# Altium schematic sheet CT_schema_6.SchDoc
size 287 x 160 mm
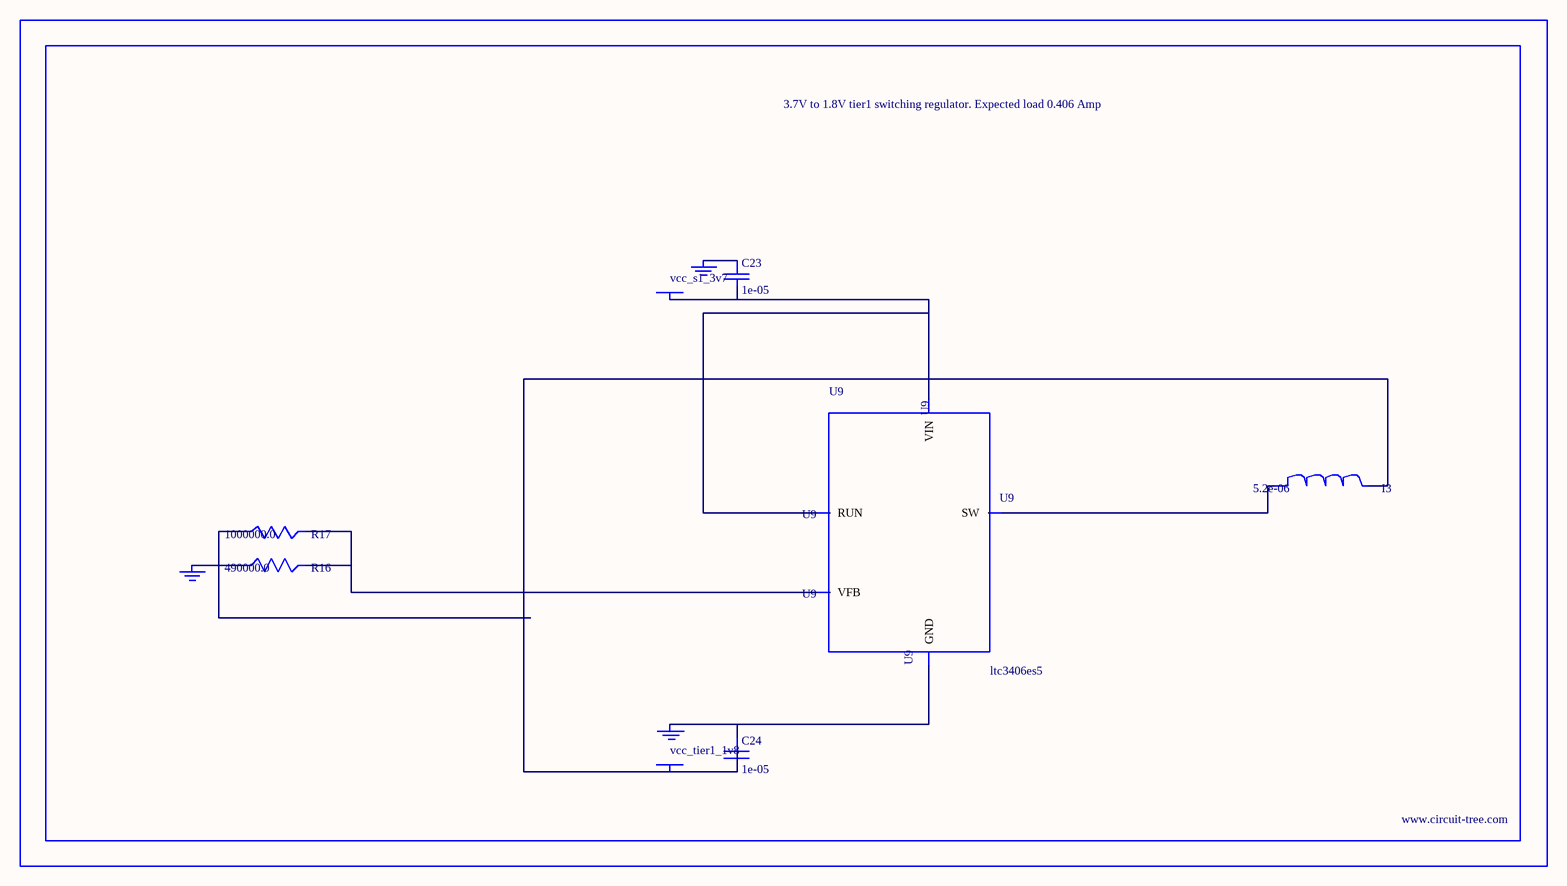
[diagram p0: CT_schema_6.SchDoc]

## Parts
BORDER5  (no value)
C23  1e-05  [C0805]
C24  1e-05  [C0805]
GND_INSTANCE_5_0  (no value)
GND_INSTANCE_5_1  (no value)
GND_INSTANCE_5_2  (no value)
I3  5.2e-06  [DR1040]
POWER_INSTANCE_5_0  vcc_tier1_1v8
POWER_INSTANCE_5_1  vcc_s1_3v7
R16  490000.0  [R0603]
R17  1000000.0  [R0603]
U9  ltc3406es5  [TSOT-23-5]

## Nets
NetC23_1: C23.1 GND_INSTANCE_5_1.0(GND)
NetC23_2: C23.2 POWER_INSTANCE_5_1.0(PWR) U9.1(RUN) U9.4(VIN)
NetC24_1: C24.1 GND_INSTANCE_5_0.0(GND) U9.2(GND)
NetC24_2: C24.2 I3.2 POWER_INSTANCE_5_0.0(PWR) R17.1
NetGND_INSTANCE_5_2_0: GND_INSTANCE_5_2.0(GND) R16.1
NetI3_1: I3.1 U9.3(SW)
NetR16_2: R16.2 R17.2 U9.5(VFB)

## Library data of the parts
BORDER5 = BORDER_PAGE5
C23 C24 = C0805C106K8RACTU
GND_INSTANCE_5_0-GND_INSTANCE_5_2 = GND
I3 = DR1040-5R2-R
POWER_INSTANCE_5_0 POWER_INSTANCE_5_1 = PWR
R16 = R16
R17 = RC0603JR-071ML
